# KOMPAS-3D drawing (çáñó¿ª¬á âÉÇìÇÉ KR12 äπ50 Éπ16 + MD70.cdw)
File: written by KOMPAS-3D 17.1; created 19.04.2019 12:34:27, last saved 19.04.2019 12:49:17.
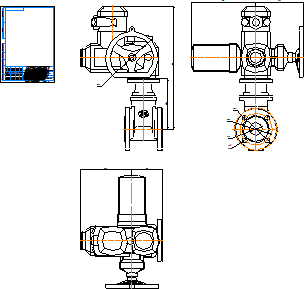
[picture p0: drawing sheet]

Sheet 1: A4, portrait

Title block, sheet 1: name: Задвижка ГРАНАР KR12 Ду50 Ру16 + / MD70; material: Внимание! Данный продукт является объектом авторского права ООО «Торговый Дом АДЛ». / Запрещается изменение, копирование, распространение / (в том числе путем копирования на другие сайты и ресурсы в Интернете) / или любое иное использование информации и объектов без предварительного / согласия правообладателя (ООО «Торговый Дом АДЛ»).; mass: 79,79; sheets: 1; organisation: ООО "Торговый дом АДЛ"; sheet format: A4; stored path: \\adlc.lan\data\АДЛ_ПКД\3D-модели\ADL production\Клиновые задвижки серии KR ГРАНАР\Клиновые задвижки KR12 с эл.приводами Смартгир\KOMPAS 2D\Задвижка ГРАНАР KR12 Ду50 Ру16 + MD70.cdw

Views: Вид 1, Проекционный вид 2, Проекционный вид 3
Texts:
  user
Dimensions and other numbers on the sheet: 196; 478; 205; 50; 19; 4 Отв.; 253; 187; 165; 125; 200; 120; 1:1; 1; 79,79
